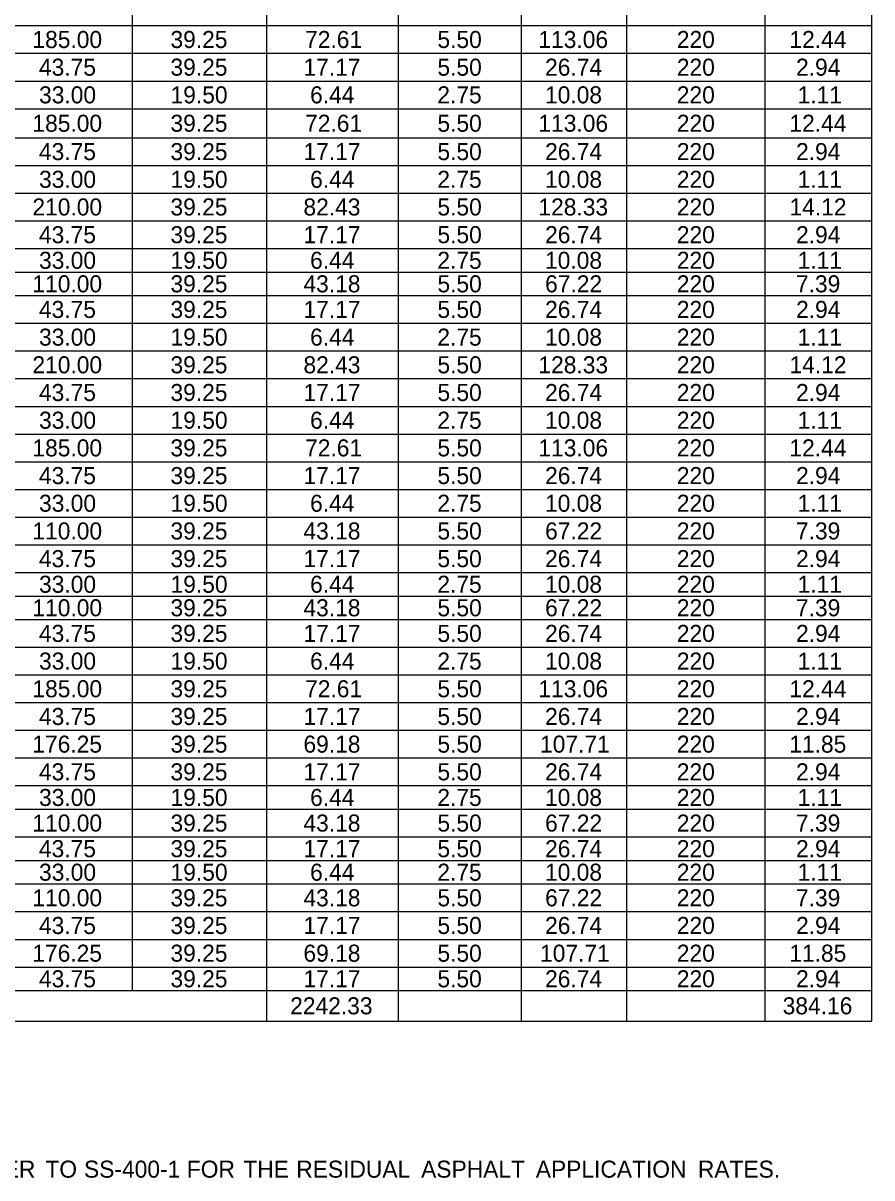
# Model space of a CAD drawing. Extents: x 544250 to 1930787, y -1948365 to 596640.
# Drawn here: x 556001.3 to 556257.5, y -1946821.4 to -1946472.9 of the extents above; entities that cross this region are included whole.
import ezdxf

# ---------------------------------------------------------------- set-up
doc = ezdxf.new("R2010")
doc.units = 0
doc.layers.add('Default', color=7, linetype='Continuous')

msp = doc.modelspace()

# ---------------------------------------------------------------- linework, layer by layer
at = {"layer": 'Default'}
for p, q in [((556034.36, -1946764.83), (556034.36, -1946131.03)), ((556114.58, -1946774.02), (556114.58, -1946131.03)), ((556257.47, -1946774.02), (556257.47, -1946131.03)), ((556074.89, -1946774.02), (556074.89, -1946153.17)), ((556151.76, -1946774.02), (556151.76, -1946153.17)), ((556183.51, -1946774.02), (556183.51, -1946153.17)), ((556225.3, -1946774.02), (556225.3, -1946153.17)), ((555848.86, -1946473.62), (556257.47, -1946473.62)), ((555848.86, -1946481.98), (556257.47, -1946481.98)), ((555672.13, -1946490.33), (556257.47, -1946490.33)), ((555848.86, -1946498.69), (556257.47, -1946498.69)), ((555848.86, -1946507.46), (556257.47, -1946507.46)), ((555848.86, -1946515.82), (556257.47, -1946515.82)), ((555848.86, -1946524.18), (556257.47, -1946524.18)), ((555848.86, -1946532.53), (556257.47, -1946532.53)), ((555848.86, -1946540.89), (556257.47, -1946540.89)), ((555848.86, -1946547.99), (556257.47, -1946547.99)), ((555848.86, -1946555.09), (556257.47, -1946555.09)), ((555848.86, -1946563.45), (556257.47, -1946563.45)), ((555848.86, -1946571.8), (556257.47, -1946571.8)), ((555848.86, -1946580.16), (556257.47, -1946580.16)), ((555672.13, -1946588.52), (556257.47, -1946588.52)), ((555848.86, -1946596.87), (556257.47, -1946596.87)), ((555848.86, -1946605.23), (556257.47, -1946605.23)), ((555848.86, -1946613.59), (556257.47, -1946613.59)), ((555848.86, -1946621.94), (556257.47, -1946621.94)), ((555848.86, -1946630.3), (556257.47, -1946630.3)), ((555848.86, -1946638.65), (556257.47, -1946638.65)), ((555848.86, -1946645.76), (556257.47, -1946645.76)), ((555848.86, -1946652.86), (556257.47, -1946652.86)), ((555848.86, -1946661.21), (556257.47, -1946661.21)), ((555848.86, -1946669.57), (556257.47, -1946669.57)), ((555848.86, -1946677.93), (556257.47, -1946677.93)), ((555672.13, -1946686.28), (556257.47, -1946686.28)), ((555848.86, -1946686.28), (556257.47, -1946686.28)), ((555848.86, -1946694.64), (556257.47, -1946694.64)), ((555848.86, -1946702.99), (556257.47, -1946702.99)), ((555848.86, -1946710.1), (556257.47, -1946710.1)), ((555848.86, -1946718.45), (556257.47, -1946718.45)), ((555848.86, -1946725.56), (556257.47, -1946725.56)), ((555848.86, -1946732.66), (556257.47, -1946732.66)), ((555848.86, -1946741.01), (556257.47, -1946741.01)), ((555848.86, -1946749.37), (556257.47, -1946749.37)), ((555848.86, -1946757.73), (556257.47, -1946757.73)), ((555672.13, -1946764.83), (556257.47, -1946764.83)), ((556074.89, -1946774.02), (556074.89, -1946764.83)), ((556151.76, -1946774.02), (556151.76, -1946764.83)), ((556183.51, -1946764.83), (556225.3, -1946764.83)), ((556183.51, -1946774.02), (556183.51, -1946764.83)), ((556225.3, -1946764.83), (556257.47, -1946764.83)), ((556225.3, -1946774.02), (556225.3, -1946764.83)), ((555672.13, -1946774.02), (556257.47, -1946774.02))]:
    msp.add_line(p, q, dxfattribs=at)

# ---------------------------------------------------------------- texts
for s, height, p in [('185.00', 5.142, (556004.12, -1946480.37)), ('39.25', 5.142, (556045.78, -1946480.37)), ('72.61', 5.142, (556086.41, -1946480.37)), ('5.50', 5.142, (556126.35, -1946480.37)), ('113.06', 5.142, (556156.82, -1946480.37)), ('220', 5.142, (556198.59, -1946480.37)), ('12.44', 5.142, (556232.57, -1946480.37)), ('43.75', 5.142, (556006.09, -1946488.73)), ('39.25', 5.142, (556045.78, -1946488.73)), ('17.17', 5.142, (556085.91, -1946488.73)), ('5.50', 5.142, (556126.35, -1946488.73)), ('26.74', 5.142, (556158.83, -1946488.73)), ('220', 5.142, (556198.59, -1946488.73)), ('2.94', 5.142, (556234.57, -1946488.73)), ('33.00', 5.142, (556006.12, -1946497.08)), ('19.50', 5.142, (556045.81, -1946497.08)), ('6.44', 5.142, (556087.92, -1946497.08)), ('2.75', 5.142, (556126.32, -1946497.08)), ('10.08', 5.142, (556158.81, -1946497.08)), ('220', 5.142, (556198.59, -1946497.08)), ('1.11', 5.142, (556235.05, -1946497.08)), ('185.00', 5.142, (556004.12, -1946505.65)), ('39.25', 5.142, (556045.78, -1946505.65)), ('72.61', 5.142, (556086.41, -1946505.65)), ('5.50', 5.142, (556126.35, -1946505.65)), ('113.06', 5.142, (556156.82, -1946505.65)), ('220', 5.142, (556198.59, -1946505.65)), ('12.44', 5.142, (556232.57, -1946505.65)), ('43.75', 5.142, (556006.09, -1946514.21)), ('39.25', 5.142, (556045.78, -1946514.21)), ('17.17', 5.142, (556085.91, -1946514.21)), ('5.50', 5.142, (556126.35, -1946514.21)), ('26.74', 5.142, (556158.83, -1946514.21)), ('220', 5.142, (556198.59, -1946514.21)), ('2.94', 5.142, (556234.57, -1946514.21)), ('33.00', 5.142, (556006.12, -1946522.57)), ('19.50', 5.142, (556045.81, -1946522.57)), ('6.44', 5.142, (556087.92, -1946522.57)), ('2.75', 5.142, (556126.32, -1946522.57)), ('10.08', 5.142, (556158.81, -1946522.57)), ('220', 5.142, (556198.59, -1946522.57)), ('1.11', 5.142, (556235.05, -1946522.57)), ('210.00', 5.142, (556004.12, -1946530.92)), ('39.25', 5.142, (556045.78, -1946530.92)), ('82.43', 5.142, (556085.91, -1946530.92)), ('5.50', 5.142, (556126.35, -1946530.92)), ('128.33', 5.142, (556156.82, -1946530.92)), ('220', 5.142, (556198.59, -1946530.92)), ('14.12', 5.142, (556232.59, -1946530.92)), ('43.75', 5.142, (556006.09, -1946539.28)), ('39.25', 5.142, (556045.78, -1946539.28)), ('17.17', 5.142, (556085.91, -1946539.28)), ('5.50', 5.142, (556126.35, -1946539.28)), ('26.74', 5.142, (556158.83, -1946539.28)), ('220', 5.142, (556198.59, -1946539.28)), ('2.94', 5.142, (556234.57, -1946539.28)), ('33.00', 5.142, (556006.12, -1946547.01)), ('19.50', 5.142, (556045.81, -1946547.01)), ('6.44', 5.142, (556087.92, -1946547.01)), ('2.75', 5.142, (556126.32, -1946547.01)), ('10.08', 5.142, (556158.81, -1946547.01)), ('220', 5.142, (556198.59, -1946547.01)), ('1.11', 5.142, (556235.05, -1946547.01)), ('110.00', 5.142, (556004.12, -1946554.11)), ('39.25', 5.142, (556045.78, -1946554.11)), ('43.18', 5.142, (556085.91, -1946554.11)), ('5.50', 5.142, (556126.35, -1946554.11)), ('67.22', 5.142, (556158.84, -1946554.11)), ('220', 5.142, (556198.59, -1946554.11)), ('7.39', 5.142, (556234.55, -1946554.11)), ('43.75', 5.142, (556006.09, -1946561.84)), ('39.25', 5.142, (556045.78, -1946561.84)), ('17.17', 5.142, (556085.91, -1946561.84)), ('5.50', 5.142, (556126.35, -1946561.84)), ('26.74', 5.142, (556158.83, -1946561.84)), ('220', 5.142, (556198.59, -1946561.84)), ('2.94', 5.142, (556234.57, -1946561.84)), ('33.00', 5.142, (556006.12, -1946570.2)), ('19.50', 5.142, (556045.81, -1946570.2)), ('6.44', 5.142, (556087.92, -1946570.2)), ('2.75', 5.142, (556126.32, -1946570.2)), ('10.08', 5.142, (556158.81, -1946570.2)), ('220', 5.142, (556198.59, -1946570.2)), ('1.11', 5.142, (556235.05, -1946570.2)), ('210.00', 5.142, (556004.12, -1946578.55)), ('39.25', 5.142, (556045.78, -1946578.55)), ('82.43', 5.142, (556085.91, -1946578.55)), ('5.50', 5.142, (556126.35, -1946578.55)), ('128.33', 5.142, (556156.82, -1946578.55)), ('220', 5.142, (556198.59, -1946578.55)), ('14.12', 5.142, (556232.59, -1946578.55)), ('43.75', 5.142, (556006.09, -1946586.91)), ('39.25', 5.142, (556045.78, -1946586.91)), ('5.50', 5.142, (556126.35, -1946586.91)), ('26.74', 5.142, (556158.83, -1946586.91)), ('220', 5.142, (556198.59, -1946586.91)), ('2.94', 5.142, (556234.57, -1946586.91)), ('17.17', 5.142, (556085.91, -1946586.91)), ('33.00', 5.142, (556006.12, -1946595.27)), ('19.50', 5.142, (556045.81, -1946595.27)), ('6.44', 5.142, (556087.92, -1946595.27)), ('2.75', 5.142, (556126.32, -1946595.27)), ('10.08', 5.142, (556158.81, -1946595.27)), ('220', 5.142, (556198.59, -1946595.27)), ('1.11', 5.142, (556235.05, -1946595.27)), ('185.00', 5.142, (556004.12, -1946603.62)), ('39.25', 5.142, (556045.78, -1946603.62)), ('72.61', 5.142, (556086.41, -1946603.62)), ('5.50', 5.142, (556126.35, -1946603.62)), ('113.06', 5.142, (556156.82, -1946603.62)), ('220', 5.142, (556198.59, -1946603.62)), ('12.44', 5.142, (556232.57, -1946603.62)), ('43.75', 5.142, (556006.09, -1946611.98)), ('39.25', 5.142, (556045.78, -1946611.98)), ('17.17', 5.142, (556085.91, -1946611.98)), ('5.50', 5.142, (556126.35, -1946611.98)), ('26.74', 5.142, (556158.83, -1946611.98)), ('220', 5.142, (556198.59, -1946611.98)), ('2.94', 5.142, (556234.57, -1946611.98)), ('33.00', 5.142, (556006.12, -1946620.33)), ('19.50', 5.142, (556045.81, -1946620.33)), ('6.44', 5.142, (556087.92, -1946620.33)), ('2.75', 5.142, (556126.32, -1946620.33)), ('10.08', 5.142, (556158.81, -1946620.33)), ('220', 5.142, (556198.59, -1946620.33)), ('1.11', 5.142, (556235.05, -1946620.33)), ('110.00', 5.142, (556004.12, -1946628.69)), ('39.25', 5.142, (556045.78, -1946628.69)), ('43.18', 5.142, (556085.91, -1946628.69)), ('5.50', 5.142, (556126.35, -1946628.69)), ('67.22', 5.142, (556158.84, -1946628.69)), ('220', 5.142, (556198.59, -1946628.69)), ('7.39', 5.142, (556234.55, -1946628.69)), ('43.75', 5.142, (556006.09, -1946637.05)), ('39.25', 5.142, (556045.78, -1946637.05)), ('17.17', 5.142, (556085.91, -1946637.05)), ('5.50', 5.142, (556126.35, -1946637.05)), ('26.74', 5.142, (556158.83, -1946637.05)), ('220', 5.142, (556198.59, -1946637.05)), ('2.94', 5.142, (556234.57, -1946637.05)), ('33.00', 5.142, (556006.12, -1946644.78)), ('19.50', 5.142, (556045.81, -1946644.78)), ('6.44', 5.142, (556087.92, -1946644.78)), ('2.75', 5.142, (556126.32, -1946644.78)), ('10.08', 5.142, (556158.81, -1946644.78)), ('220', 5.142, (556198.59, -1946644.78)), ('1.11', 5.142, (556235.05, -1946644.78)), ('110.00', 5.142, (556004.12, -1946651.88)), ('39.25', 5.142, (556045.78, -1946651.88)), ('43.18', 5.142, (556085.91, -1946651.88)), ('5.50', 5.142, (556126.35, -1946651.88)), ('67.22', 5.142, (556158.84, -1946651.88)), ('220', 5.142, (556198.59, -1946651.88)), ('7.39', 5.142, (556234.55, -1946651.88)), ('43.75', 5.142, (556006.09, -1946659.61)), ('39.25', 5.142, (556045.78, -1946659.61)), ('17.17', 5.142, (556085.91, -1946659.61)), ('5.50', 5.142, (556126.35, -1946659.61)), ('26.74', 5.142, (556158.83, -1946659.61)), ('220', 5.142, (556198.59, -1946659.61)), ('2.94', 5.142, (556234.57, -1946659.61)), ('33.00', 5.142, (556006.12, -1946667.96)), ('19.50', 5.142, (556045.81, -1946667.96)), ('6.44', 5.142, (556087.92, -1946667.96)), ('2.75', 5.142, (556126.32, -1946667.96)), ('10.08', 5.142, (556158.81, -1946667.96)), ('220', 5.142, (556198.59, -1946667.96)), ('1.11', 5.142, (556235.05, -1946667.96)), ('185.00', 5.142, (556004.12, -1946676.32)), ('39.25', 5.142, (556045.78, -1946676.32)), ('72.61', 5.142, (556086.41, -1946676.32)), ('5.50', 5.142, (556126.35, -1946676.32)), ('113.06', 5.142, (556156.82, -1946676.32)), ('220', 5.142, (556198.59, -1946676.32)), ('12.44', 5.142, (556232.57, -1946676.32)), ('43.75', 5.142, (556006.09, -1946684.68)), ('39.25', 5.142, (556045.78, -1946684.68)), ('17.17', 5.142, (556085.91, -1946684.68)), ('5.50', 5.142, (556126.35, -1946684.68)), ('26.74', 5.142, (556158.83, -1946684.68)), ('220', 5.142, (556198.59, -1946684.68)), ('2.94', 5.142, (556234.57, -1946684.68)), ('176.25', 5.142, (556004.09, -1946693.03)), ('39.25', 5.142, (556045.78, -1946693.03)), ('69.18', 5.142, (556085.91, -1946693.03)), ('5.50', 5.142, (556126.35, -1946693.03)), ('107.71', 5.142, (556157.32, -1946693.03)), ('220', 5.142, (556198.59, -1946693.03)), ('11.85', 5.142, (556232.54, -1946693.03)), ('43.75', 5.142, (556006.09, -1946701.39)), ('39.25', 5.142, (556045.78, -1946701.39)), ('17.17', 5.142, (556085.91, -1946701.39)), ('5.50', 5.142, (556126.35, -1946701.39)), ('26.74', 5.142, (556158.83, -1946701.39)), ('220', 5.142, (556198.59, -1946701.39)), ('2.94', 5.142, (556234.57, -1946701.39)), ('33.00', 5.142, (556006.12, -1946709.12)), ('19.50', 5.142, (556045.81, -1946709.12)), ('6.44', 5.142, (556087.92, -1946709.12)), ('2.75', 5.142, (556126.32, -1946709.12)), ('10.08', 5.142, (556158.81, -1946709.12)), ('220', 5.142, (556198.59, -1946709.12)), ('1.11', 5.142, (556235.05, -1946709.12)), ('110.00', 5.142, (556004.12, -1946716.85)), ('39.25', 5.142, (556045.78, -1946716.85)), ('43.18', 5.142, (556085.91, -1946716.85)), ('5.50', 5.142, (556126.35, -1946716.85)), ('67.22', 5.142, (556158.84, -1946716.85)), ('220', 5.142, (556198.59, -1946716.85)), ('7.39', 5.142, (556234.55, -1946716.85)), ('43.75', 5.142, (556006.09, -1946724.58)), ('39.25', 5.142, (556045.78, -1946724.58)), ('17.17', 5.142, (556085.91, -1946724.58)), ('5.50', 5.142, (556126.35, -1946724.58)), ('26.74', 5.142, (556158.83, -1946724.58)), ('220', 5.142, (556198.59, -1946724.58)), ('2.94', 5.142, (556234.57, -1946724.58)), ('33.00', 5.142, (556006.12, -1946731.68)), ('19.50', 5.142, (556045.81, -1946731.68)), ('6.44', 5.142, (556087.92, -1946731.68)), ('2.75', 5.142, (556126.32, -1946731.68)), ('10.08', 5.142, (556158.81, -1946731.68)), ('220', 5.142, (556198.59, -1946731.68)), ('1.11', 5.142, (556235.05, -1946731.68)), ('110.00', 5.142, (556004.12, -1946739.41)), ('39.25', 5.142, (556045.78, -1946739.41)), ('43.18', 5.142, (556085.91, -1946739.41)), ('5.50', 5.142, (556126.35, -1946739.41)), ('67.22', 5.142, (556158.84, -1946739.41)), ('220', 5.142, (556198.59, -1946739.41)), ('7.39', 5.142, (556234.55, -1946739.41)), ('43.75', 5.142, (556006.09, -1946747.76)), ('39.25', 5.142, (556045.78, -1946747.76)), ('17.17', 5.142, (556085.91, -1946747.76)), ('5.50', 5.142, (556126.35, -1946747.76)), ('26.74', 5.142, (556158.83, -1946747.76)), ('220', 5.142, (556198.59, -1946747.76)), ('2.94', 5.142, (556234.57, -1946747.76)), ('176.25', 5.142, (556004.09, -1946756.12)), ('39.25', 5.142, (556045.78, -1946756.12)), ('69.18', 5.142, (556085.91, -1946756.12)), ('5.50', 5.142, (556126.35, -1946756.12)), ('107.71', 5.142, (556157.32, -1946756.12)), ('220', 5.142, (556198.59, -1946756.12)), ('11.85', 5.142, (556232.54, -1946756.12)), ('43.75', 5.142, (556006.09, -1946763.85)), ('39.25', 5.142, (556045.78, -1946763.85)), ('17.17', 5.142, (556085.91, -1946763.85)), ('5.50', 5.142, (556126.35, -1946763.85)), ('26.74', 5.142, (556158.83, -1946763.85)), ('220', 5.142, (556198.59, -1946763.85)), ('2.94', 5.142, (556234.57, -1946763.85)), ('2242.33', 5.142, (556081.91, -1946772)), ('384.16', 5.142, (556230.53, -1946772)), ('  REFER', 5.142, (555977.88, -1946821.3)), (' TO', 5.142, (556006.13, -1946821.3)), (' SS-400-1', 5.142, (556017.78, -1946821.3)), (' FOR', 5.142, (556048.8, -1946821.3)), (' THE', 5.142, (556065.86, -1946821.3)), (' RESIDUAL', 5.142, (556081.84, -1946821.3)), (' ASPHALT', 5.142, (556119.52, -1946821.3)), (' APPLICATION', 5.1422, (556154.12, -1946821.3)), (' RATES.', 5.142, (556203.04, -1946821.3))]:
    msp.add_text(s, height=height, dxfattribs=at).set_placement(p)

doc.saveas('drawing.dxf')
